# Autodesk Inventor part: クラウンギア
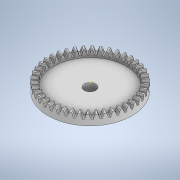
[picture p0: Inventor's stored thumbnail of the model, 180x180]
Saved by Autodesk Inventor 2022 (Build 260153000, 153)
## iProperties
Created: 2024-11
Part Number: クラウンギア
Material: 一般
Document SubType Name: Modeling
Designer: jsat7
Density: 1 g/cm^3
Appearance: 既定
Author: jsat7
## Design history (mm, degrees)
sketch "スケッチ1"
  geometry: L1 (0, 0)-(-16.481, 0); L2 (0, 0)-(-15.194, -0.569); L3 (0, 0)-(-15.177, 0.568); C1 r 9.5 at (0, 0); A1 r 11 centre (0, 0) between (-10.992, 0.411) and (-10.992, -0.411); 1 further point
  constraints: 6 end point, 2 centre point, 2 coincident, 2 point on circle, 2 point on line, 1 horizontal
  dimensions: "d0" = 22 diameter of A1; "d1" = 19 diameter of C1; "d2" = 2.14286 deg angle of L1 L2; "d3" = 2.14286 deg angle of L3 L1 (= d2)
node "作業平面1"
sketch "スケッチ3"
  geometry: L1 (0.515, 0)-(0.291, 0) reference; L2 (0.5, 0.6)-(0.5, 0); L3 (0.5, -0.6)-(0.5, 0); L4 (0, 0.151)-(0, -0.212) reference; L5 (0.5, 0.6)-(0, 0.411); L6 (0, 0.411)-(-0.625, 0.175); L7 (0.5, -0.6)-(0, -0.411); L8 (0, -0.411)-(-0.625, -0.175); L9 (-0.625, 0.175)-(-0.625, -0.175); C1 r 0.002 at (0, 0.411); C2 r 0.002 at (0, -0.411); 5 further points
  constraints: 18 end point, 4 point on line, 3 vertical, 2 centre point, 2 horizontal, 1 collinear, 1 perpendicular, 2 other
  dimensions: "d5" = 0.00409 diameter of C1; "d6" = 0.6 distance from line of L1 L2.start; "d7" = 0.6 distance from line of L1 L3.start; "d8" = 0.5 distance between parallel lines of L4 L2; "d9" = 0.625 distance between parallel lines of L9 L4
extrude "押し出し1" new body sketch "スケッチ1" distance "d10" = 0.5; taper "d12" = 0 deg; dims "d11" = 2.125, "d13" = 0
extrude "押し出し2" cut sketch "スケッチ3" distance "d14" = 2; taper "d15" = 0 deg
node "作業平面2"
sketch "スケッチ4"
  geometry: C1 r 9.5 at (0, 0); 1 further point
  constraints: 1 centre point, 1 coincident
extrude "押し出し3" join sketch "スケッチ4" distance "d17" = 1; taper "d18" = 0 deg
sketch "スケッチ5"
  geometry: C1 r 1.5 at (0, 0); 1 further point
  constraints: 1 centre point, 1 coincident
  dimensions: "d22" = 3 diameter of C1
extrude "押し出し4" cut sketch "スケッチ5" distance "d23" = 1; taper "d24" = 0 deg
sketch "スケッチ6"
  geometry: C1 r 1.5 at (0, 0) reference; C2 r 2.4 at (0, 0); C3 r 1.5 at (0, 0); 1 further point
  constraints: 2 centre point, 2 coincident, 1 concentric
  dimensions: "d25" = 4.8 diameter of C2
extrude "押し出し5" join sketch "スケッチ6" distance "d26" = 1.9; taper "d27" = 0 deg
node "ソリッド1"
sketch "スケッチ2"
  geometry: 1 further point
pattern_circular "円形状パターン1" dims angle "d20" = 360 deg
other parameters: "d4" = 11, "d16" = 0
